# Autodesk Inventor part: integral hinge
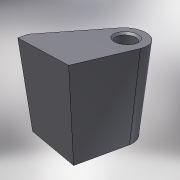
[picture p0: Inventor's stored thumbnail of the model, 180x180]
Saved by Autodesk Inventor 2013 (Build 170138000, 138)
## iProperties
Created: 2005-10
Part Number: integral hinge
Material: Steel, Mild
Document SubType Name: Modeling
Designer: =<Author>
Manufacturer: Standard
Standards Organization: Custom
Description: =<Part Number>
Density: 7.86 g/cm^3
Mass: 361.235 g
Surface Area: 98.6012 cm^2
Volume: 45.9587 cm^3
Author: PVitaliy
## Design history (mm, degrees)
sketch "Эскиз2"
  geometry: L1 (0, 0)-(30, 0); L2 (30, 0)-(39.428, 26.667); L3 (0, 5)-(21.844, 35.787); L4 (0, 0)-(0, 5); C1 r 5 at (30, 30); A1 r 10 centre (30, 30) between (39.428, 26.667) and (21.844, 35.787)
  constraints: 8 end point, 2 centre point, 2 point on circle, 2 tangent, 1 coincident, 1 horizontal, 1 vertical, 1 other
  dimensions: "d0" = 30 distance of L1.start L1.end; "d1" = 10 diameter of C1; "d2" = 10 radius of A1; "d3" = 5 distance of L1.start L3.start; "d4" = 30 distance from line of A1.centre L1; "d8" = 30 distance from line of L4 A1.centre
extrude "Выдавливание1" new body sketch "Эскиз2" distance "d5" = 50; taper "d6" = 0 deg
chamfer "Фаска1" distance "d9" = 1; stored, may be unused: second distance "d10" = 2, angle "d11" = 45 deg
body "Solid1"
